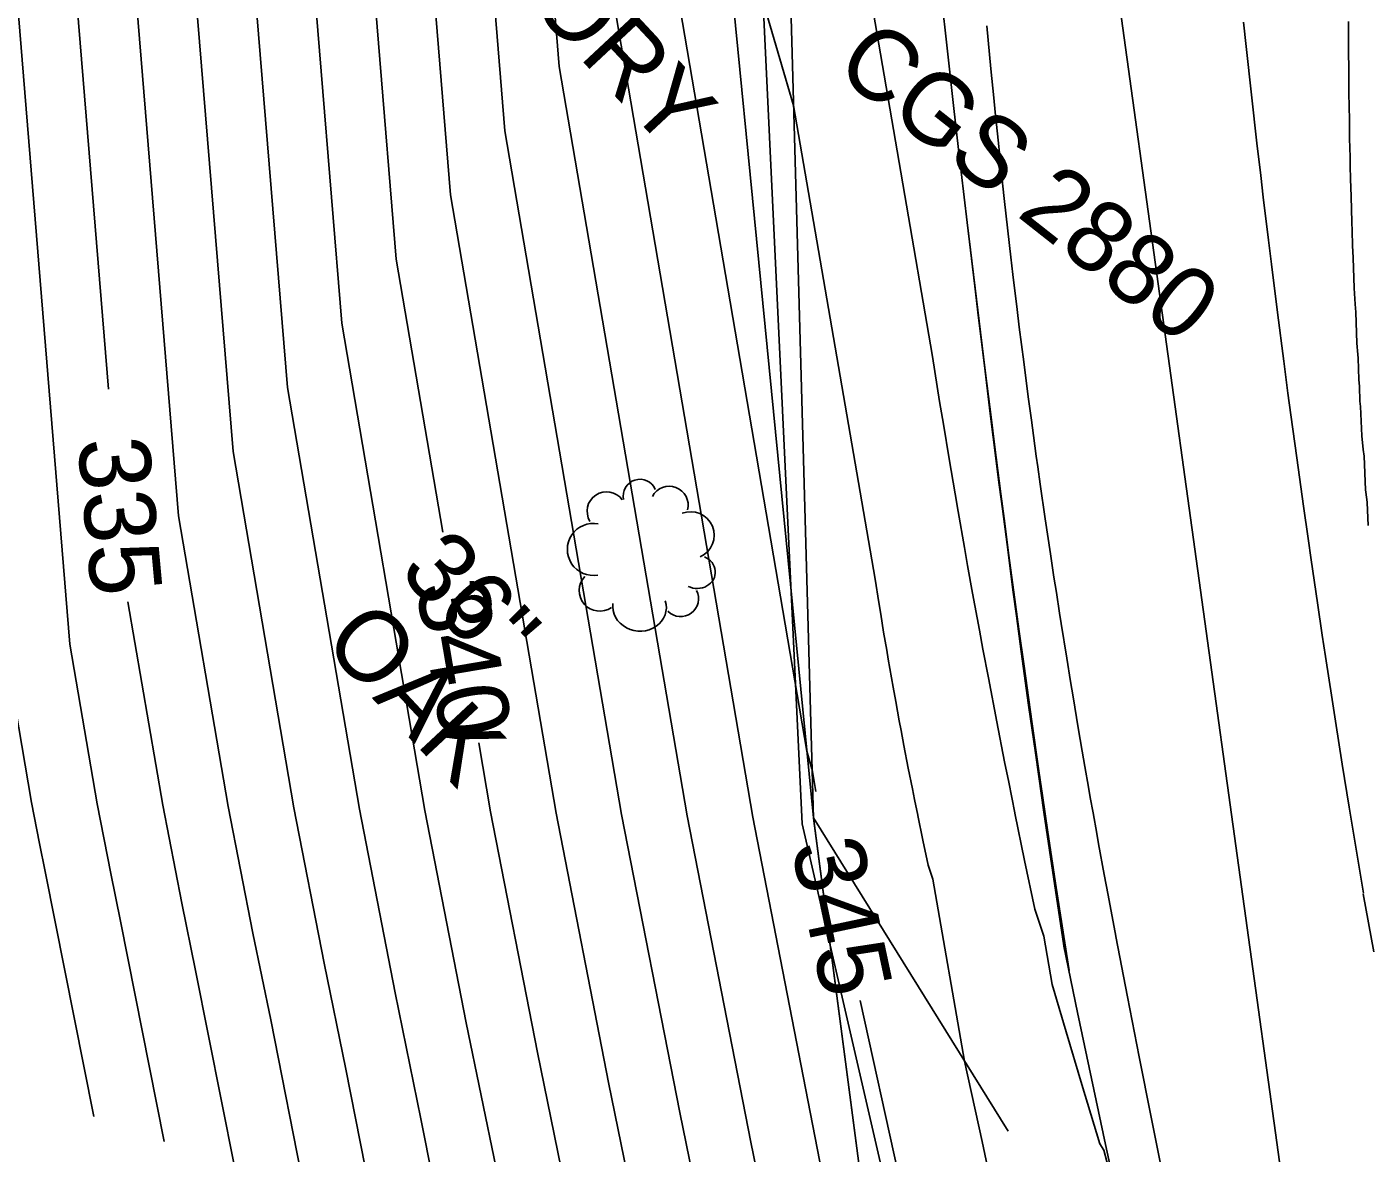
# Model space of a CAD drawing. Extents: x 487096 to 489566, y 221939 to 224454.
# Drawn here: x 488356.5 to 488416.7, y 222860.8 to 222911.5 of the extents above; entities that cross this region are included whole.
import ezdxf

# ---------------------------------------------------------------- set-up
doc = ezdxf.new("R2010")
doc.units = 0
for name, color, linetype in [('SV_BKLN_EARTH_TOP', 7, 'Continuous'), ('SV_FENC_FENCES', 7, 'Continuous'), ('SV_GEOD_CTGS_TX', 7, 'Continuous'), ('SV_ROAD_BITRD', 7, 'Continuous'), ('SV_ROWL_HWYLOC', 7, 'Continuous'), ('SV_SURF_INDEX_CONTOUR', 7, 'Continuous'), ('SV_SURF_INTER_CONTOUR', 7, 'Continuous'), ('SV_TRAF_PVMTL', 7, 'Continuous'), ('SV_TREE_TREEVEG', 7, 'Continuous'), ('SV_TREE_TREEVEG_TX', 7, 'Continuous'), ('SV_UTOH_OVERHEAD_LINES', 7, 'Continuous')]:
    doc.layers.add(name, color=color, linetype=linetype)

msp = doc.modelspace()

# ---------------------------------------------------------------- linework, layer by layer
at = {"layer": 'SV_BKLN_EARTH_TOP'}
msp.add_lwpolyline([(488391.814, 222875.894), (488390.567, 222921.008), (488388.639, 223000.073), (488389.407, 223042.325), (488396.478, 223078.484), (488405.528, 223123.261), (488407.475, 223152.677)], dxfattribs=at)
at = {"layer": 'SV_FENC_FENCES'}
for points in [[(488400.559, 222861.835), (488391.815, 222875.913), (488387.651, 222918.235), (488386.769, 222964.099), (488384.515, 222999.563), (488389.407, 223042.325), (488396.478, 223078.484), (488402.804, 223123.48), (488407.475, 223152.677), (488415.007, 223209.78), (488415.388, 223241.145)], [(488391.047, 222851.299), (488394, 222859.238), (488391.814, 222875.894)]]:
    msp.add_lwpolyline(points, dxfattribs=at)
at = {"layer": 'SV_ROAD_BITRD'}
for points in [[(488397.554, 222912.926), (488397.835, 222910.359), (488398.124, 222907.794), (488398.32, 222906.084), (488398.453, 222904.945), (488398.721, 222902.666), (488399.076, 222899.709), (488399.256, 222898.231), (488399.531, 222896.014), (488399.809, 222893.798), (488399.95, 222892.69), (488400.237, 222890.475), (488400.381, 222889.368), (488400.601, 222887.707), (488400.899, 222885.494), (488401.05, 222884.387), (488401.28, 222882.728), (488401.63, 222880.24), (488401.948, 222878.029), (488402.109, 222876.923), (488402.354, 222875.266), (488402.728, 222872.78), (488403.111, 222870.295), (488403.306, 222869.053)], [(488397.554, 222912.926), (488397.835, 222910.359), (488398.124, 222907.794), (488398.32, 222906.084), (488398.453, 222904.945), (488398.721, 222902.666), (488399.076, 222899.709), (488399.256, 222898.231), (488399.531, 222896.014), (488399.809, 222893.798), (488399.95, 222892.69), (488400.237, 222890.475), (488400.381, 222889.368), (488400.601, 222887.707), (488400.899, 222885.494), (488401.05, 222884.387), (488401.28, 222882.728), (488401.63, 222880.24), (488401.948, 222878.029), (488402.109, 222876.923), (488402.354, 222875.266), (488402.728, 222872.78), (488403.111, 222870.295), (488403.306, 222869.053)], [(488397.56, 222912.927), (488397.84, 222910.36), (488398.128, 222907.795), (488398.323, 222906.085), (488398.455, 222904.945), (488398.721, 222902.666), (488399.061, 222899.806), (488399.233, 222898.377), (488399.495, 222896.233), (488399.761, 222894.09), (488399.895, 222893.018), (488400.167, 222890.876), (488400.304, 222889.805), (488400.513, 222888.199), (488400.795, 222886.058), (488400.938, 222884.988), (488401.155, 222883.383), (488401.486, 222880.976), (488401.786, 222878.837), (488401.938, 222877.768), (488402.169, 222876.165), (488402.521, 222873.76), (488402.882, 222871.357), (488403.065, 222870.155)], [(488403.063, 222870.144), (488403.68, 222867.173), (488404.305, 222864.204), (488404.937, 222861.236), (488405.578, 222858.271), (488406.226, 222855.306), (488406.882, 222852.344), (488407.546, 222849.383), (488408.218, 222846.424), (488408.898, 222843.467), (488409.585, 222840.511), (488410.28, 222837.558), (488410.983, 222834.606), (488411.694, 222831.656), (488412.413, 222828.708), (488413.139, 222825.762), (488413.873, 222822.817), (488414.615, 222819.875), (488415.364, 222816.935), (488416.122, 222813.997), (488416.887, 222811.06)]]:
    msp.add_lwpolyline(points, dxfattribs=at)
at = {"layer": 'SV_ROWL_HWYLOC'}
msp.add_lwpolyline([(488415.388, 223241.145), (488415.007, 223209.78), (488407.475, 223152.677), (488402.804, 223123.48), (488396.478, 223078.484), (488389.407, 223042.325), (488386.961, 223020.944), (488384.515, 222999.563), (488386.769, 222964.099), (488387.651, 222918.235), (488391.815, 222875.913), (488394, 222859.238), (488415.207, 222774.386)], dxfattribs=at)
at = {"layer": 'SV_SURF_INDEX_CONTOUR'}
for points in [[(488349.178, 222980.783), (488355.841, 222944.471), (488357.935, 222922.292), (488360.157, 222895.18)], [(488364.437, 222974.386), (488368.457, 222952.478), (488371.483, 222920.442), (488373.074, 222901.024), (488375.167, 222888.746)], [(488391.924, 222877.1), (488391.755, 222878.086), (488391.753, 222878.109), (488391.517, 222878.914), (488385.288, 222915.445), (488385.03, 222918.592), (488381.074, 222960.484), (488380.671, 222962.679)], [(488361.027, 222885.62), (488362.585, 222876.484), (488363.445, 222872.074), (488364.062, 222869.055), (488365.806, 222860.252)], [(488376.781, 222879.283), (488377.309, 222876.186), (488379.42, 222865.363), (488380.934, 222857.953), (488381.588, 222854.654)], [(488406.866, 222826.665), (488406.187, 222828.776), (488405.531, 222830.831), (488404.897, 222832.832), (488404.284, 222834.782), (488403.692, 222836.682), (488403.119, 222838.534), (488402.565, 222840.341), (488402.029, 222842.103), (488401.511, 222843.823), (488401.01, 222845.501), (488400.524, 222847.141), (488400.055, 222848.741), (488397.964, 222852.177), (488396.113, 222857.643), (488395.64, 222859.887), (488393.918, 222867.71)]]:
    msp.add_lwpolyline(points, dxfattribs=at)
at = {"layer": 'SV_SURF_INTER_CONTOUR'}
for points in [[(488362.65, 222861.371), (488360.688, 222871.276), (488360.25, 222873.416), (488359.64, 222876.543), (488358.417, 222883.719), (488355.226, 222922.662), (488353.317, 222942.87), (488343.604, 222995.808), (488343.286, 223008.32), (488343.416, 223033.623), (488341.252, 223049.902), (488337.647, 223079.891), (488337.729, 223100.914), (488343.218, 223121.569), (488334.614, 223158.85), (488333.233, 223169.056), (488330.101, 223193.591), (488324.969, 223208.359), (488320.919, 223265.032)], [(488359.493, 222862.491), (488357.313, 222873.496), (488357.055, 222874.759), (488356.696, 222876.603), (488355.974, 222880.835), (488352.517, 222923.032), (488350.794, 222941.269), (488340.348, 222998.2), (488340.073, 223009.002), (488340.186, 223030.848), (488337.437, 223051.527), (488334.438, 223076.477), (488334.549, 223105.228), (488338.983, 223121.913), (488332.033, 223152.03), (488329.684, 223169.381), (488326.947, 223190.824), (488320.594, 223209.107), (488317.309, 223255.078)], [(488330.362, 223253.848), (488333.719, 223206.864), (488336.408, 223199.126), (488339.342, 223176.141), (488341.304, 223168.886), (488341.3, 223168.777), (488341.297, 223168.703), (488341.254, 223167.912), (488342.109, 223162.381), (488351.687, 223120.879), (488344.088, 223092.286), (488344.066, 223086.717), (488348.882, 223046.653), (488349.877, 223039.173), (488349.711, 223006.955), (488350.116, 222991.025), (488358.364, 222946.073), (488360.645, 222921.922), (488363.302, 222889.487), (488365.53, 222876.424), (488366.64, 222870.732), (488367.437, 222866.835), (488368.962, 222859.132)], [(488372.119, 222858.013), (488370.811, 222864.614), (488369.835, 222869.39), (488368.475, 222876.365), (488365.745, 222892.371), (488363.354, 222921.552), (488360.887, 222947.674), (488353.372, 222988.633), (488352.924, 223006.273), (488353.107, 223041.947), (488352.698, 223045.029), (488348.943, 223076.261), (488347.531, 223089.211), (488348.287, 223091.807), (488355.921, 223120.534), (488348.771, 223151.516), (488346.419, 223166.724), (488346.539, 223168.899), (488346.547, 223169.1), (488346.559, 223169.401), (488341.163, 223189.349), (488339.561, 223201.893), (488338.094, 223206.116), (488336.262, 223231.758)], [(488384.744, 222853.534), (488384.309, 222855.733), (488382.615, 222864.021), (488380.254, 222876.127), (488375.517, 222903.908), (488374.192, 222920.072), (488370.98, 222954.079), (488366.396, 222979.065), (488365.774, 223003.544)], [(488368.987, 223002.861), (488369.652, 222976.673), (488373.504, 222955.68), (488376.902, 222919.702), (488377.959, 222906.792), (488383.199, 222876.068), (488385.81, 222862.679), (488387.683, 222853.512), (488387.901, 222852.415)], [(488372.199, 223002.179), (488372.908, 222974.281), (488376.027, 222957.282), (488379.611, 222919.332), (488380.402, 222909.677), (488386.143, 222876.008), (488389.005, 222861.336), (488391.053, 222851.316), (488391.058, 222851.3), (488391.061, 222851.295), (488391.069, 222851.269), (488391.073, 222851.259)], [(488375.412, 223001.496), (488376.164, 222971.889), (488378.55, 222958.883), (488382.32, 222918.962), (488382.845, 222912.561), (488389.088, 222875.949), (488392.2, 222859.994), (488392.938, 222856.383), (488394.511, 222851.739), (488395.558, 222850.018), (488395.793, 222849.216), (488396.036, 222848.395), (488396.287, 222847.555), (488396.547, 222846.693), (488396.815, 222845.811), (488397.093, 222844.906), (488397.379, 222843.979), (488397.676, 222843.027), (488397.983, 222842.051), (488398.301, 222841.048), (488398.629, 222840.019), (488398.969, 222838.962)], [(488375.275, 222856.893), (488374.185, 222862.394), (488373.03, 222868.047), (488371.419, 222876.305), (488368.188, 222895.256), (488366.064, 222921.182), (488363.411, 222949.275), (488356.628, 222986.241)], [(488359.884, 222983.849), (488365.934, 222950.877), (488368.773, 222920.812), (488370.631, 222898.14), (488374.364, 222876.246), (488376.225, 222866.705), (488377.56, 222860.173), (488378.431, 222855.773)], [(488387.853, 222918.427), (488390.928, 222907.928), (488390.929, 222907.921), (488394.584, 222886.641), (488394.751, 222885.595), (488394.838, 222885.066), (488394.971, 222884.263), (488395.109, 222883.449), (488395.18, 222883.037), (488395.326, 222882.204), (488395.401, 222881.782), (488395.517, 222881.142), (488395.676, 222880.275), (488395.758, 222879.835), (488395.884, 222879.167), (488396.08, 222878.146), (488396.262, 222877.218), (488396.356, 222876.745), (488396.5, 222876.027), (488396.503, 222876.016), (488396.729, 222874.914), (488396.965, 222873.782), (488397.176, 222873.153), (488398.601, 222864.983), (488399.395, 222861.374), (488400.952, 222853.99)], [(488394.499, 222912.162), (488397.166, 222896.64), (488397.488, 222894.62), (488397.655, 222893.597), (488397.913, 222892.046), (488398.18, 222890.473), (488398.317, 222889.678), (488398.599, 222888.067), (488398.744, 222887.252), (488398.967, 222886.016), (488399.275, 222884.34), (488399.433, 222883.491), (488399.676, 222882.2), (488400.055, 222880.227), (488400.407, 222878.433), (488400.588, 222877.521), (488400.867, 222876.133), (488400.868, 222876.131), (488401.303, 222874.003), (488401.759, 222871.817), (488402.166, 222870.603), (488402.545, 222868.428), (488403.172, 222866.305), (488403.878, 222863.935), (488404.68, 222861.272), (488404.863, 222860.978), (488405.543, 222858.433)], [(488416.737, 222889.052), (488416.695, 222890.084), (488416.674, 222890.226), (488416.614, 222890.654), (488416.554, 222892.172), (488416.515, 222892.472), (488416.445, 222893.078), (488416.394, 222894.405), (488416.369, 222894.643), (488416.346, 222895.29), (488416.314, 222895.614), (488416.282, 222896.569), (488416.266, 222896.736), (488416.223, 222897.241), (488416.178, 222898.641), (488416.151, 222898.992), (488416.104, 222899.708), (488416.065, 222901.071), (488416.034, 222901.633), (488416.017, 222902.297), (488415.999, 222902.682), (488415.972, 222903.833), (488415.944, 222904.632), (488415.932, 222905.195), (488415.921, 222905.607), (488415.905, 222906.433), (488415.891, 222907.286), (488415.872, 222908.484), (488415.868, 222909.377), (488415.854, 222910.524), (488415.858, 222911.141), (488415.853, 222911.695)]]:
    msp.add_lwpolyline(points, dxfattribs=at)
at = {"layer": 'SV_TRAF_PVMTL'}
for points in [[(488399.613, 222911.505), (488399.793, 222909.564), (488399.918, 222908.27), (488399.982, 222907.623), (488400.08, 222906.653), (488400.214, 222905.36), (488400.282, 222904.714), (488400.387, 222903.745), (488400.549, 222902.292), (488400.684, 222901.112), (488400.777, 222900.326), (488400.966, 222898.755), (488401.063, 222897.97), (488401.262, 222896.4), (488401.467, 222894.831), (488401.607, 222893.785), (488401.702, 222893.088), (488401.83, 222892.159), (488401.895, 222891.694), (488402.006, 222890.911), (488402.233, 222889.344), (488402.465, 222887.778), (488402.623, 222886.734), (488402.73, 222886.039), (488402.875, 222885.111), (488402.947, 222884.648), (488403.197, 222883.084), (488403.367, 222882.042), (488403.482, 222881.347), (488403.636, 222880.421), (488403.714, 222879.958), (488403.892, 222878.916), (488404.011, 222878.222), (488404.173, 222877.297), (488404.254, 222876.834), (488404.377, 222876.14), (488404.542, 222875.215), (488404.626, 222874.753), (488404.879, 222873.366), (488405.05, 222872.442), (488405.398, 222870.594)], [(488416.523, 222872.533), (488415.885, 222876.396), (488415.574, 222878.328), (488415.269, 222880.26), (488415.119, 222881.226), (488414.822, 222883.158), (488414.676, 222884.124), (488414.46, 222885.573), (488414.177, 222887.505), (488414.037, 222888.471), (488413.831, 222889.92), (488413.528, 222892.094), (488413.265, 222894.026), (488413.135, 222894.993), (488412.944, 222896.442), (488412.664, 222898.616), (488412.391, 222900.79), (488412.257, 222901.877), (488412.025, 222903.81), (488411.911, 222904.776), (488411.743, 222906.226), (488411.498, 222908.401), (488411.26, 222910.576), (488411.144, 222911.663)], [(488416.519, 222872.501), (488416.996, 222869.89)], [(488405.399, 222870.578), (488405.92, 222867.872), (488406.449, 222865.168), (488406.986, 222862.465), (488407.53, 222859.763), (488408.083, 222857.063), (488408.643, 222854.365), (488409.211, 222851.669), (488409.787, 222848.974), (488410.371, 222846.281), (488410.963, 222843.589), (488411.562, 222840.899), (488412.169, 222838.211), (488412.784, 222835.525), (488413.407, 222832.841), (488414.037, 222830.158), (488414.676, 222827.477), (488415.322, 222824.798), (488415.976, 222822.121), (488416.637, 222819.446), (488417.307, 222816.773)]]:
    msp.add_lwpolyline(points, dxfattribs=at)
at = {"layer": 'SV_TREE_TREEVEG'}
msp.add_line((488384.135, 222887.728), (488384.135, 222887.728), dxfattribs=at)
msp.add_lwpolyline([(488469.572, 222626.729), (488414.357, 222775.799), (488391.306, 222875.646), (488384.757, 223013.776), (488396.275, 223079.007), (488413.65, 223210.141), (488414.482, 223247.549), (488427.956, 223341.619), (488424.883, 223443.612), (488411.442, 223499.763), (488395.395, 223528.757), (488373.339, 223524.504)], dxfattribs=at)
for centre, radius, start, end in [((488384.024, 222890.379), 0.75, 23.2911, 192.35792), ((488382.524, 222889.692), 0.874, 35.99331, 211.459), ((488385.339, 222889.965), 0.85, 345.53076, 152.70931), ((488386.3, 222888.61), 1.059, 294.18586, 111.10825), ((488381.935, 222887.974), 1.171, 79.3292, 279.98885), ((488382.218, 222886.125), 0.922, 137.01566, 304.55007)]:
    msp.add_arc(centre, radius, start, end, dxfattribs=at)
for centre, major_axis, ratio, start_param, end_param in [((488386.59, 222886.961), (0.822, -0.013), 0.901056, 4.216583, 7.444153), ((488384.006, 222885.393), (-1.196, 0.159), 0.902156, 0, 3.5401), ((488385.854, 222885.759), (0.08, -0.798), 0.999752, 5.391582, 8.241319)]:
    msp.add_ellipse(centre, major_axis=major_axis, ratio=ratio, start_param=start_param, end_param=end_param, dxfattribs=at)
at = {"layer": 'SV_UTOH_OVERHEAD_LINES'}
msp.add_lwpolyline([(488477.012, 222631.438), (488424.125, 222778.25), (488391.68, 223012.955), (488449.873, 223205.72), (488469.995, 223438.334), (488349.561, 223622.886), (488159.178, 223693.118), (487993.175, 223755.783), (487804.196, 223830.216), (487742.262, 223860.212)], dxfattribs=at)

# ---------------------------------------------------------------- texts
at = {"layer": 'SV_GEOD_CTGS_TX'}
msp.add_text('CGS 2880', height=3.2, rotation=321.7571, dxfattribs=at).set_placement((488392.676, 222909.474))
at = {"layer": 'SV_SURF_INDEX_CONTOUR'}
for s, rotation, p in [('335', 275.20151, (488358.758, 222892.895)), ('340', 279.67713, (488373.951, 222886.359)), ('345', 281.98857, (488390.806, 222874.666))]:
    msp.add_text(s, height=3.2, rotation=rotation, dxfattribs=at).set_placement(p)
at = {"layer": 'SV_TREE_TREEVEG_TX'}
for s, p in [('HICKORY', (488371.995, 222920.021)), ('36"', (488373.131, 222886.95)), ('OAK', (488369.696, 222883.742))]:
    msp.add_text(s, height=3.2, rotation=313.03859, dxfattribs=at).set_placement(p)

doc.saveas('drawing.dxf')
